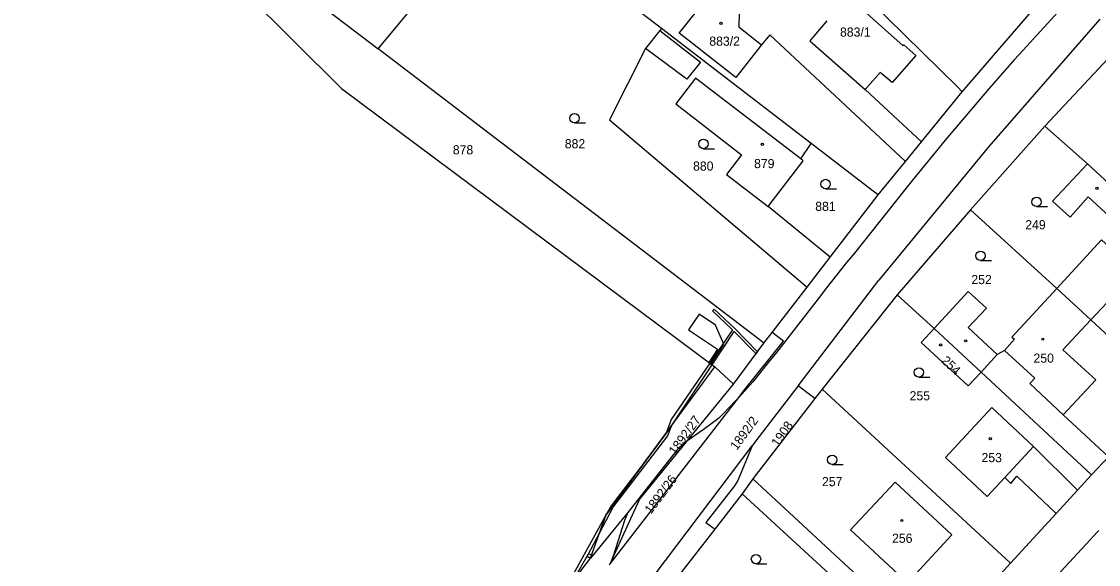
# Model space of a CAD drawing. Extents: x -587171 to -555306, y -1167727 to -1074732.
# Drawn here: x -560388 to -560216.2, y -1077787.1 to -1077700.6 of the extents above; entities that cross this region are included whole.
import ezdxf

# ---------------------------------------------------------------- set-up
doc = ezdxf.new("R2010")
doc.units = 0
for name, color, linetype in [('Hranice parcel', 7, 'Continuous'), ('Parcelní čísla', 7, 'Continuous'), ('Vnitřní kresba', 7, 'Continuous'), ('Věcná břemena k části', 7, 'Continuous'), ('Značky budov', 7, 'Continuous'), ('Značky kultur', 7, 'Continuous')]:
    doc.layers.add(name, color=color, linetype=linetype)

msp = doc.modelspace()

# ---------------------------------------------------------------- linework, layer by layer
at = {"layer": 'Hranice parcel'}
for p, q in [((-560285.91, -1077701.68), (-560311.93, -1077681.72)), ((-560331.1, -1077704.9), (-560322.05, -1077694.02)), ((-560262.02, -1077720.01), (-560285.91, -1077701.68)), ((-560273.55, -1077701.41), (-560269.95, -1077704.27)), ((-560212.28, -1077703.89), (-560224.74, -1077717.23)), ((-560244.43, -1077719.71), (-560237.94, -1077711.73)), ((-560224.74, -1077717.23), (-560236.6, -1077730.58)), ((-560224.74, -1077717.23), (-560217.97, -1077723.25)), ((-560263.69, -1077722.44), (-560262.02, -1077720.01)), ((-560246.98, -1077722.84), (-560244.43, -1077719.71)), ((-560251.34, -1077728.2), (-560246.98, -1077722.84)), ((-560258.99, -1077738.11), (-560251.34, -1077728.2)), ((-560258.99, -1077738.11), (-560268.91, -1077730.03)), ((-560236.6, -1077730.58), (-560248.32, -1077744.1)), ((-560236.6, -1077730.58), (-560222.87, -1077743.11)), ((-560262.68, -1077742.89), (-560258.99, -1077738.11)), ((-560268.24, -1077750.1), (-560262.68, -1077742.89)), ((-560222.87, -1077743.11), (-560217.41, -1077748.11)), ((-560248.32, -1077744.1), (-560260.28, -1077759.18)), ((-560248.32, -1077744.1), (-560242.41, -1077749.49)), ((-560217.41, -1077748.11), (-560204.98, -1077759.69)), ((-560269.56, -1077751.81), (-560268.24, -1077750.1)), ((-560266.43, -1077751.52), (-560268.24, -1077750.1)), ((-560242.41, -1077749.49), (-560234.92, -1077756.43)), ((-560272.86, -1077759.54), (-560266.43, -1077751.52)), ((-560234.92, -1077756.43), (-560217.33, -1077772.84)), ((-560294.11, -1077787.02), (-560273.58, -1077760.47)), ((-560273.58, -1077760.47), (-560272.86, -1077759.54)), ((-560260.28, -1077759.18), (-560261.42, -1077760.66)), ((-560260.28, -1077759.18), (-560230.24, -1077786.92)), ((-560261.42, -1077760.66), (-560271.34, -1077773.46)), ((-560217.33, -1077772.84), (-560214.61, -1077769.95)), ((-560271.34, -1077773.46), (-560273.01, -1077775.84)), ((-560271.34, -1077773.46), (-560242.43, -1077800.19)), ((-560219.53, -1077775.24), (-560217.33, -1077772.84)), ((-560273.01, -1077775.84), (-560277.4, -1077781.48)), ((-560273.01, -1077775.84), (-560244.32, -1077802.19)), ((-560222.97, -1077778.99), (-560219.53, -1077775.24)), ((-560291.27, -1077778.84), (-560297.22, -1077786.08)), ((-560230.24, -1077786.92), (-560222.97, -1077778.99)), ((-560277.4, -1077781.48), (-560284.5, -1077790.6)), ((-560387.98, -1077904.93), (-560297.22, -1077786.08)), ((-560294.23, -1077787.18), (-560294.11, -1077787.02)), ((-560242.43, -1077800.19), (-560230.24, -1077786.92))]:
    msp.add_line(p, q, dxfattribs=at)
for points in [[(-560237.94, -1077711.73), (-560238.65, -1077711.03), (-560292.32, -1077658.28)], [(-560362.63, -1077676.58), (-560360.56, -1077681.04), (-560358.52, -1077683.18), (-560356.35, -1077685.14), (-560347.27, -1077692.56), (-560331.1, -1077704.9)], [(-560270.16, -1077686.56), (-560268.62, -1077684.55), (-560264.69, -1077687.95), (-560259.99, -1077692.27), (-560260.7, -1077693.04), (-560253.79, -1077698.88), (-560253.69, -1077698.77), (-560247.36, -1077704.43), (-560247.23, -1077704.28), (-560245.33, -1077705.94), (-560249.1, -1077710.26), (-560251, -1077708.68), (-560253.4, -1077711.37), (-560244.43, -1077719.71)], [(-560359.92, -1077688.39), (-560336.97, -1077711.25), (-560277.37, -1077755.62)], [(-560280.97, -1077704.03), (-560283.06, -1077702.4), (-560277.84, -1077695.75), (-560275.86, -1077697.3)], [(-560237.94, -1077711.73), (-560225.25, -1077697), (-560225.93, -1077696.26)], [(-560275.86, -1077697.3), (-560273.52, -1077699.14), (-560273.55, -1077701.41)], [(-560221.55, -1077697.81), (-560228.2, -1077705.12), (-560229.65, -1077706.68), (-560233, -1077710.48), (-560233.72, -1077711.32), (-560240.9, -1077719.8), (-560242.03, -1077721.14), (-560245.88, -1077725.84), (-560247.13, -1077727.44), (-560255.12, -1077737.45), (-560256.37, -1077738.99), (-560259.58, -1077743.01), (-560260.93, -1077744.74), (-560267.57, -1077753.31), (-560268.85, -1077754.85), (-560271.33, -1077758.01), (-560272.61, -1077759.42), (-560273.58, -1077760.47)], [(-560285.91, -1077701.68), (-560286.17, -1077702), (-560288.45, -1077704.85), (-560294.19, -1077716.21), (-560262.68, -1077742.89)], [(-560246.98, -1077722.84), (-560268.65, -1077702.65), (-560269.95, -1077704.27)], [(-560269.56, -1077751.81), (-560270.36, -1077751.2), (-560331.1, -1077704.9)], [(-560269.95, -1077704.27), (-560274.06, -1077709.48), (-560277.71, -1077706.6), (-560280.97, -1077704.03)], [(-560263.69, -1077722.44), (-560280.46, -1077709.59), (-560283.62, -1077713.69), (-560273.12, -1077721.79), (-560275.55, -1077724.94), (-560268.91, -1077730.03)], [(-560251.34, -1077728.2), (-560252.13, -1077727.59), (-560262.02, -1077720.01)], [(-560268.91, -1077730.03), (-560263.3, -1077722.74), (-560263.69, -1077722.44)], [(-560217.97, -1077723.25), (-560223.55, -1077729.19), (-560220.74, -1077731.73), (-560217.83, -1077728.5), (-560213.06, -1077732.88), (-560208.06, -1077737.72), (-560210.41, -1077740.22), (-560215.73, -1077735.36), (-560222.87, -1077743.11)], [(-560217.97, -1077723.25), (-560210.51, -1077730.09), (-560192.87, -1077746.51)], [(-560222.87, -1077743.11), (-560230.01, -1077750.86), (-560229.61, -1077751.21), (-560231.17, -1077753), (-560232.35, -1077753.64), (-560236.98, -1077749.3), (-560234.09, -1077746.23), (-560236.98, -1077743.61), (-560242.41, -1077749.49)], [(-560217.41, -1077748.11), (-560213.03, -1077743.44), (-560207.88, -1077748.18), (-560202.83, -1077742.6), (-560195.14, -1077748.98)], [(-560214.61, -1077769.95), (-560221.81, -1077763.23), (-560216.65, -1077757.65), (-560221.87, -1077752.88), (-560217.41, -1077748.11)], [(-560242.41, -1077749.49), (-560244.46, -1077751.71), (-560236.97, -1077758.65), (-560234.92, -1077756.43)], [(-560277.37, -1077755.62), (-560274.43, -1077758.34), (-560269.56, -1077751.81)], [(-560297.22, -1077786.08), (-560294.8, -1077779.23), (-560277.37, -1077755.62)], [(-560261.42, -1077760.66), (-560262.74, -1077759.68), (-560264.13, -1077758.65), (-560267.52, -1077763.05), (-560270.86, -1077767.38), (-560271.43, -1077768.18), (-560273.73, -1077773.72), (-560274.27, -1077774.57), (-560278.83, -1077780.42), (-560277.52, -1077781.39), (-560277.4, -1077781.48)], [(-560273.58, -1077760.47), (-560274.04, -1077760.97), (-560276.1, -1077763.16), (-560276.83, -1077763.82), (-560279.24, -1077765.63), (-560281.84, -1077767.46), (-560282.52, -1077767.93), (-560283.26, -1077768.61), (-560286.8, -1077773.12), (-560291.27, -1077778.84)], [(-560219.53, -1077775.24), (-560226.58, -1077768.28), (-560233.23, -1077762.1), (-560240.61, -1077770.04), (-560233.94, -1077776.27), (-560231.16, -1077773.25), (-560230.16, -1077774.21), (-560229.25, -1077773.01), (-560222.97, -1077778.99)], [(-560246.69, -1077790.05), (-560239.57, -1077782.38), (-560248.65, -1077773.96), (-560255.78, -1077781.6), (-560246.69, -1077790.05)], [(-560291.27, -1077778.84), (-560291.83, -1077780.08), (-560293.54, -1077785.61), (-560294.11, -1077787.02)], [(-560224.86, -1077791.11), (-560218.17, -1077783.87), (-560216.42, -1077781.98), (-560216.14, -1077781.67)]]:
    msp.add_lwpolyline(points, dxfattribs=at)
at = {"layer": 'Vnitřní kresba'}
for p, q in [((-560215.97, -1077700.17), (-560233.67, -1077720.45)), ((-560286.17, -1077702), (-560279.7, -1077707.04)), ((-560259.52, -1077700.43), (-560262.24, -1077703.64)), ((-560262.24, -1077703.64), (-560253.4, -1077711.37)), ((-560281.84, -1077709.76), (-560288.45, -1077704.85)), ((-560279.7, -1077707.04), (-560281.84, -1077709.76)), ((-560233.67, -1077720.45), (-560251.25, -1077741.77)), ((-560264.13, -1077758.65), (-560251.25, -1077741.77)), ((-560232.35, -1077753.64), (-560234.92, -1077756.43)), ((-560231.17, -1077753), (-560226.37, -1077757.42)), ((-560226.37, -1077757.42), (-560227.14, -1077758.26)), ((-560227.14, -1077758.26), (-560221.81, -1077763.23)), ((-560286.91, -1077788.65), (-560271.43, -1077768.18)), ((-560231.16, -1077773.25), (-560226.58, -1077768.28))]:
    msp.add_line(p, q, dxfattribs=at)
msp.add_lwpolyline([(-560294.11, -1077787.02), (-560289.4, -1077776.76), (-560274.43, -1077758.34)], dxfattribs=at)
at = {"layer": 'Věcná břemena k části'}
for points in [[(-560270.83, -1077753.51), (-560270.59, -1077753.19), (-560274.2, -1077749.51), (-560277.49, -1077746.39), (-560277.77, -1077746.67), (-560274.6, -1077749.68), (-560278.22, -1077754.99), (-560284.35, -1077763.99), (-560285.16, -1077766.18), (-560284.3, -1077765.01), (-560277.83, -1077755.27), (-560274.31, -1077749.97)], [(-560276.99, -1077752.78), (-560278.37, -1077754.88), (-560278.01, -1077755.15), (-560275.98, -1077751.97), (-560277.31, -1077748.95), (-560279.89, -1077747.22), (-560281.58, -1077749.7)], [(-560295.86, -1077782.24), (-560293.59, -1077777.96), (-560284.9, -1077766.62), (-560284.3, -1077765.01), (-560285.16, -1077766.18), (-560287.74, -1077769.67), (-560294.8, -1077779.23)], [(-560287.74, -1077769.67), (-560293.92, -1077777.74), (-560294.8, -1077779.23)], [(-560295.86, -1077782.24), (-560294.8, -1077779.23), (-560300.82, -1077790.23), (-560307.8, -1077799.93), (-560300.23, -1077790.02), (-560297.74, -1077785.77), (-560297.55, -1077785.42)], [(-560295.86, -1077782.24), (-560294.8, -1077779.23), (-560300.82, -1077790.23), (-560307.8, -1077799.93), (-560300.23, -1077790.02), (-560297.74, -1077785.77), (-560297.22, -1077786.08), (-560297.05, -1077785.61), (-560297.55, -1077785.42)]]:
    msp.add_lwpolyline(points, close=True, dxfattribs=at)
at = {"layer": 'Značky budov'}
for centre in [(-560276.42, -1077700.85), (-560269.81, -1077720.12), (-560216.45, -1077727.15), (-560241.36, -1077752.1), (-560237.38, -1077751.45), (-560225.08, -1077751.18), (-560233.44, -1077767.04), (-560247.57, -1077780.09)]:
    msp.add_circle(centre, 0.175, dxfattribs=at)
at = {"layer": 'Značky kultur'}
for p, q in [((-560299.8, -1077716.72), (-560298.05, -1077716.72)), ((-560279.22, -1077720.82), (-560277.47, -1077720.82)), ((-560259.74, -1077727.2), (-560257.99, -1077727.2)), ((-560226.08, -1077730.05), (-560224.33, -1077730.05)), ((-560235.01, -1077738.64), (-560233.26, -1077738.64)), ((-560244.84, -1077757.24), (-560243.09, -1077757.24)), ((-560258.67, -1077771.16), (-560256.92, -1077771.16)), ((-560270.83, -1077786.99), (-560269.08, -1077786.99))]:
    msp.add_line(p, q, dxfattribs=at)
for centre in [(-560299.8, -1077715.97), (-560279.22, -1077720.07), (-560259.74, -1077726.45), (-560226.08, -1077729.3), (-560235.01, -1077737.89), (-560244.84, -1077756.49), (-560258.67, -1077770.41), (-560270.83, -1077786.24)]:
    msp.add_circle(centre, 0.75, dxfattribs=at)

# ---------------------------------------------------------------- texts
at = {"layer": 'Parcelní čísla'}
for s, p in [('883/1', (-560257.43, -1077702.96)), ('883/2', (-560278.28, -1077704.41)), ('882', (-560301.33, -1077720.76)), ('878', (-560319.19, -1077721.73)), ('879', (-560271.14, -1077723.92)), ('880', (-560280.87, -1077724.32)), ('881', (-560261.38, -1077730.74)), ('249', (-560227.88, -1077733.67)), ('252', (-560236.48, -1077742.41)), ('250', (-560226.57, -1077754.94)), ('255', (-560246.33, -1077760.94)), ('253', (-560234.86, -1077770.79)), ('257', (-560260.3, -1077774.62)), ('256', (-560249.13, -1077783.65))]:
    msp.add_text(s, height=1.46, dxfattribs=at).set_placement(p)
for s, rotation, p in [('254', 316, (-560241.39, -1077754.75)), ('1892/27', 54, (-560283.7, -1077769.77)), ('1892/2', 54, (-560273.9, -1077769.01)), ('1908', 55, (-560267.31, -1077768.47)), ('1892/26', 53, (-560287.59, -1077779.17))]:
    msp.add_text(s, height=1.46, rotation=rotation, dxfattribs=at).set_placement(p)

doc.saveas('drawing.dxf')
